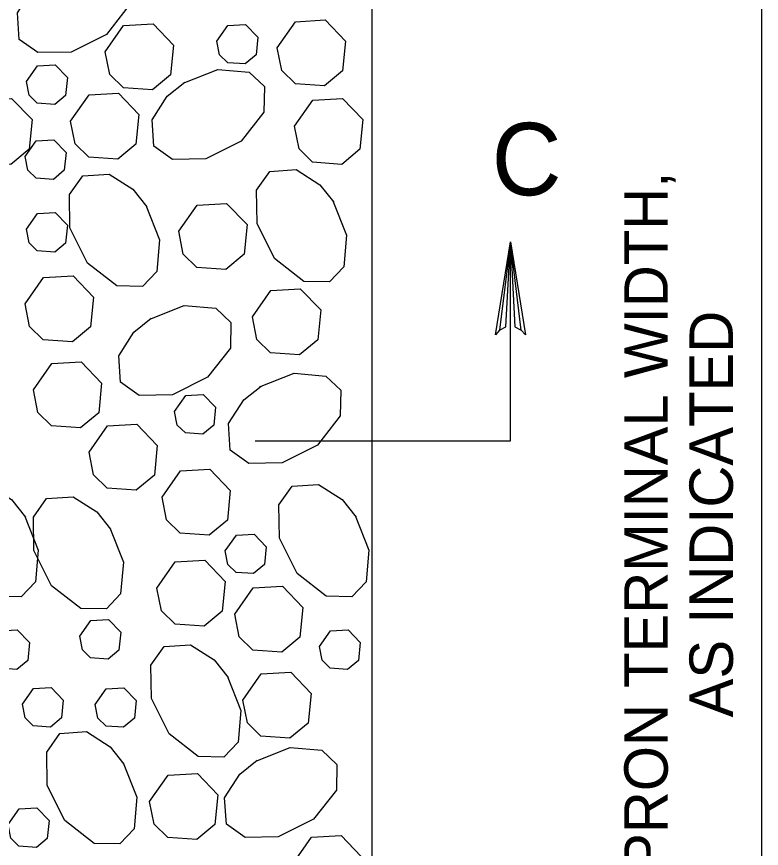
# Model space of a CAD drawing. Extents: x 636183 to 639890, y 299162 to 300538.
# Drawn here: x 638823.6 to 638875.1, y 299737.2 to 299794.6 of the extents above; entities that cross this region are included whole.
import ezdxf

# ---------------------------------------------------------------- set-up
doc = ezdxf.new("R2010")
doc.units = 0
doc.layers.add('Default', color=7, linetype='Continuous')

msp = doc.modelspace()

# ---------------------------------------------------------------- linework, layer by layer
at = {"layer": 'Default'}
for p, q in [((638848.199, 299678.562), (638848.199, 299851.41)), ((638875.054, 299851.41), (638875.054, 299678.562)), ((638857.742, 299765.288), (638857.742, 299779.024)), ((638840.105, 299765.288), (638857.742, 299765.288))]:
    msp.add_line(p, q, dxfattribs=at)
for points in [[(638825.855, 299797.36), (638828.232, 299798.302), (638830.415, 299798.113), (638831.453, 299797.126), (638831.42, 299795.355), (638829.845, 299793.341), (638827.411, 299792.125), (638825.118, 299792.084), (638823.826, 299793.002), (638823.704, 299794.829), (638824.751, 299796.463), (638825.951, 299797.42)], [(638841.636, 299792.415), (638842.906, 299794.222), (638844.935, 299794.338), (638846.344, 299792.876), (638846.14, 299790.827), (638844.887, 299789.785), (638842.885, 299789.93), (638841.942, 299790.843), (638841.637, 299792.415)], [(638829.763, 299792.14), (638831.034, 299793.947), (638833.062, 299794.064), (638834.473, 299792.601), (638834.269, 299790.552), (638833.016, 299789.51), (638831.012, 299789.656), (638830.07, 299790.569), (638829.764, 299792.14)], [(638837.472, 299792.883), (638838.234, 299793.967), (638839.451, 299794.037), (638840.298, 299793.159), (638840.175, 299791.931), (638839.424, 299791.305), (638838.221, 299791.392), (638837.656, 299791.94), (638837.473, 299792.882)], [(638824.322, 299790.081), (638825.084, 299791.166), (638826.301, 299791.235), (638827.147, 299790.358), (638827.025, 299789.129), (638826.273, 299788.503), (638825.071, 299788.59), (638824.506, 299789.138), (638824.323, 299790.081)], [(638835.148, 299789.987), (638837.525, 299790.929), (638839.708, 299790.74), (638840.746, 299789.754), (638840.713, 299787.982), (638839.138, 299785.969), (638836.704, 299784.752), (638834.41, 299784.712), (638833.119, 299785.629), (638832.997, 299787.457), (638834.045, 299789.09), (638835.245, 299790.048)], [(638827.373, 299787.358), (638828.643, 299789.166), (638830.671, 299789.282), (638832.082, 299787.82), (638831.878, 299785.771), (638830.625, 299784.729), (638828.622, 299784.874), (638827.68, 299785.788), (638827.374, 299787.358)], [(638820.002, 299787.004), (638821.272, 299788.812), (638823.3, 299788.927), (638824.71, 299787.465), (638824.506, 299785.417), (638823.253, 299784.374), (638821.251, 299784.519), (638820.309, 299785.433), (638820.003, 299787.004)], [(638842.831, 299787.004), (638844.101, 299788.812), (638846.13, 299788.927), (638847.54, 299787.465), (638847.336, 299785.417), (638846.083, 299784.374), (638844.08, 299784.519), (638843.138, 299785.433), (638842.832, 299787.004)], [(638824.233, 299784.915), (638824.996, 299785.998), (638826.213, 299786.068), (638827.06, 299785.191), (638826.937, 299783.962), (638826.185, 299783.337), (638824.983, 299783.424), (638824.418, 299783.972), (638824.234, 299784.914)], [(638845.475, 299781.855), (638846.417, 299779.479), (638846.228, 299777.295), (638845.242, 299776.258), (638843.47, 299776.291), (638841.457, 299777.866), (638840.24, 299780.3), (638840.2, 299782.593), (638841.117, 299783.885), (638842.945, 299784.007), (638844.578, 299782.96), (638845.536, 299781.76)], [(638832.562, 299781.548), (638833.505, 299779.172), (638833.316, 299776.988), (638832.33, 299775.95), (638830.558, 299775.984), (638828.545, 299777.558), (638827.328, 299779.992), (638827.288, 299782.286), (638828.205, 299783.577), (638830.032, 299783.699), (638831.666, 299782.652), (638832.623, 299781.452)], [(638834.845, 299779.75), (638836.115, 299781.558), (638838.144, 299781.673), (638839.554, 299780.211), (638839.35, 299778.163), (638838.097, 299777.12), (638836.094, 299777.265), (638835.152, 299778.179), (638834.846, 299779.75)], [(638824.322, 299779.888), (638825.084, 299780.973), (638826.301, 299781.042), (638827.147, 299780.165), (638827.025, 299778.936), (638826.273, 299778.31), (638825.071, 299778.397), (638824.506, 299778.945), (638824.323, 299779.888)], [(638856.976, 299772.922), (638857.417, 299773.149), (638857.742, 299779.024), (638856.976, 299772.922), (638856.708, 299772.609), (638857.742, 299779.024), (638858.032, 299773.154), (638858.469, 299772.939), (638857.742, 299779.024), (638858.761, 299772.609), (638858.469, 299772.939)], [(638824.238, 299774.754), (638825.509, 299776.561), (638827.537, 299776.677), (638828.948, 299775.215), (638828.744, 299773.166), (638827.491, 299772.124), (638825.487, 299772.269), (638824.545, 299773.183), (638824.239, 299774.753)], [(638839.929, 299773.859), (638841.199, 299775.666), (638843.228, 299775.781), (638844.638, 299774.32), (638844.434, 299772.271), (638843.181, 299771.229), (638841.179, 299771.373), (638840.237, 299772.287), (638839.93, 299773.858)], [(638832.843, 299773.693), (638835.219, 299774.635), (638837.403, 299774.446), (638838.44, 299773.46), (638838.407, 299771.688), (638836.832, 299769.675), (638834.398, 299768.458), (638832.105, 299768.418), (638830.813, 299769.335), (638830.691, 299771.163), (638831.739, 299772.796), (638832.938, 299773.754)], [(638824.803, 299768.808), (638826.074, 299770.616), (638828.103, 299770.731), (638829.513, 299769.269), (638829.309, 299767.221), (638828.056, 299766.178), (638826.053, 299766.323), (638825.11, 299767.237), (638824.804, 299768.808)], [(638840.422, 299769.009), (638842.798, 299769.951), (638844.982, 299769.762), (638846.019, 299768.776), (638845.986, 299767.004), (638844.411, 299764.991), (638841.977, 299763.774), (638839.684, 299763.734), (638838.392, 299764.651), (638838.27, 299766.478), (638839.318, 299768.112), (638840.517, 299769.069)], [(638834.553, 299767.325), (638835.315, 299768.41), (638836.533, 299768.479), (638837.378, 299767.602), (638837.256, 299766.373), (638836.504, 299765.747), (638835.302, 299765.834), (638834.737, 299766.382), (638834.554, 299767.325)], [(638828.648, 299764.507), (638829.919, 299766.315), (638831.947, 299766.43), (638833.357, 299764.968), (638833.153, 299762.92), (638831.9, 299761.878), (638829.897, 299762.022), (638828.955, 299762.936), (638828.649, 299764.507)], [(638833.686, 299761.403), (638834.957, 299763.21), (638836.984, 299763.326), (638838.395, 299761.864), (638838.191, 299759.815), (638836.938, 299758.773), (638834.935, 299758.918), (638833.993, 299759.832), (638833.687, 299761.403)], [(638824.193, 299760.127), (638825.136, 299757.751), (638824.947, 299755.567), (638823.96, 299754.529), (638822.188, 299754.563), (638820.176, 299756.137), (638818.959, 299758.571), (638818.918, 299760.865), (638819.836, 299762.156), (638821.663, 299762.278), (638823.297, 299761.231), (638824.254, 299760.031)], [(638847.022, 299760.127), (638847.965, 299757.751), (638847.776, 299755.567), (638846.79, 299754.529), (638845.018, 299754.563), (638843.005, 299756.137), (638841.788, 299758.571), (638841.748, 299760.865), (638842.665, 299762.156), (638844.493, 299762.278), (638846.126, 299761.231), (638847.084, 299760.031)], [(638830.073, 299759.282), (638831.015, 299756.905), (638830.827, 299754.721), (638829.841, 299753.684), (638828.069, 299753.717), (638826.056, 299755.292), (638824.839, 299757.726), (638824.799, 299760.019), (638825.716, 299761.311), (638827.543, 299761.433), (638829.178, 299760.386), (638830.135, 299759.186)], [(638838.051, 299757.7), (638838.814, 299758.784), (638840.031, 299758.854), (638840.876, 299757.977), (638840.755, 299756.747), (638840.002, 299756.122), (638838.801, 299756.21), (638838.235, 299756.758), (638838.052, 299757.7)], [(638833.33, 299755.128), (638834.6, 299756.934), (638836.629, 299757.051), (638838.039, 299755.589), (638837.835, 299753.539), (638836.582, 299752.497), (638834.579, 299752.643), (638833.637, 299753.556), (638833.331, 299755.127)], [(638838.698, 299753.333), (638839.969, 299755.14), (638841.997, 299755.256), (638843.408, 299753.794), (638843.204, 299751.745), (638841.951, 299750.703), (638839.948, 299750.848), (638839.006, 299751.762), (638838.699, 299753.332)], [(638828.003, 299751.803), (638828.765, 299752.886), (638829.983, 299752.956), (638830.828, 299752.078), (638830.705, 299750.85), (638829.954, 299750.225), (638828.752, 299750.312), (638828.186, 299750.86), (638828.003, 299751.802)], [(638821.713, 299751.09), (638822.476, 299752.175), (638823.693, 299752.245), (638824.539, 299751.367), (638824.417, 299750.138), (638823.665, 299749.512), (638822.463, 299749.6), (638821.898, 299750.148), (638821.714, 299751.09)], [(638844.543, 299751.09), (638845.306, 299752.175), (638846.523, 299752.245), (638847.368, 299751.367), (638847.246, 299750.138), (638846.494, 299749.512), (638845.292, 299749.6), (638844.727, 299750.148), (638844.544, 299751.09)], [(638838.183, 299749.06), (638839.127, 299746.683), (638838.938, 299744.499), (638837.951, 299743.462), (638836.179, 299743.495), (638834.166, 299745.07), (638832.95, 299747.503), (638832.909, 299749.797), (638833.827, 299751.088), (638835.654, 299751.211), (638837.288, 299750.163), (638838.245, 299748.963)], [(638839.264, 299747.387), (638840.534, 299749.195), (638842.563, 299749.31), (638843.973, 299747.848), (638843.769, 299745.8), (638842.516, 299744.757), (638840.513, 299744.902), (638839.571, 299745.816), (638839.264, 299747.387)], [(638824.044, 299747.111), (638824.806, 299748.195), (638826.024, 299748.265), (638826.869, 299747.387), (638826.747, 299746.159), (638825.995, 299745.533), (638824.793, 299745.62), (638824.227, 299746.168), (638824.044, 299747.11)], [(638829.075, 299747.096), (638829.837, 299748.18), (638831.054, 299748.25), (638831.901, 299747.372), (638831.778, 299746.144), (638831.027, 299745.518), (638829.825, 299745.605), (638829.259, 299746.153), (638829.076, 299747.095)], [(638830.995, 299743.064), (638831.938, 299740.688), (638831.749, 299738.504), (638830.762, 299737.466), (638828.99, 299737.499), (638826.977, 299739.075), (638825.761, 299741.509), (638825.72, 299743.802), (638826.638, 299745.094), (638828.465, 299745.216), (638830.099, 299744.169), (638831.056, 299742.969)], [(638840.152, 299743.185), (638842.529, 299744.127), (638844.712, 299743.938), (638845.749, 299742.952), (638845.716, 299741.18), (638844.141, 299739.167), (638841.708, 299737.95), (638839.414, 299737.91), (638838.123, 299738.827), (638838, 299740.655), (638839.048, 299742.288), (638840.248, 299743.245)], [(638832.825, 299740.398), (638834.096, 299742.206), (638836.125, 299742.321), (638837.534, 299740.86), (638837.33, 299738.811), (638836.077, 299737.769), (638834.074, 299737.913), (638833.132, 299738.827), (638832.827, 299740.398)], [(638823.055, 299738.799), (638823.817, 299739.882), (638825.035, 299739.952), (638825.88, 299739.074), (638825.758, 299737.846), (638825.006, 299737.221), (638823.804, 299737.308), (638823.238, 299737.856), (638823.055, 299738.798)], [(638842.74, 299736.118), (638844.011, 299737.926), (638846.039, 299738.042), (638847.429, 299736.601)]]:
    msp.add_lwpolyline(points, dxfattribs=at)

# ---------------------------------------------------------------- texts
msp.add_text('C', height=4.997, dxfattribs=at).set_placement((638856.435, 299782.241))
for s, p in [('APRON TERMINAL WIDTH,', (638868.592, 299732.863)), ('AS INDICATED', (638873.089, 299746.201))]:
    msp.add_text(s, height=2.99804, rotation=90, dxfattribs=at).set_placement(p)

doc.saveas('drawing.dxf')
